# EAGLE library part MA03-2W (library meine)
PIN HEADER
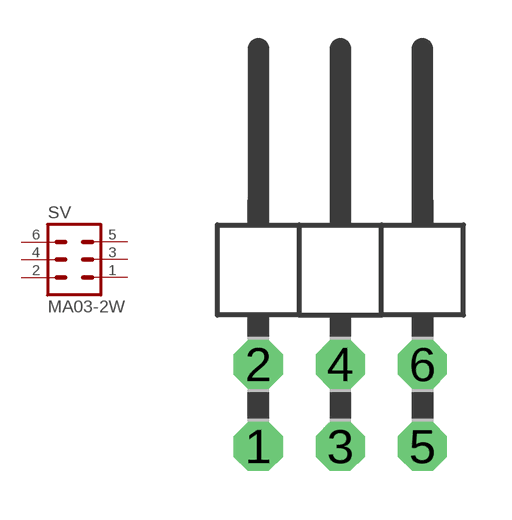
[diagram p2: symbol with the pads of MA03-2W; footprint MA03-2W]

Designator prefix SV

## MA03-2W  [MA03-2W]
1  1  pas
2  2  pas
3  3  pas
4  4  pas
5  5  pas
6  6  pas

## Footprint MA03-2W (pad centres in mm)
PIN HEADER
drill 1.016 octagon: 1 -2.54,-1.27; 2 -2.54,1.27; 3 0,-1.27; 4 0,1.27; 5 2.54,-1.27; 6 2.54,1.27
